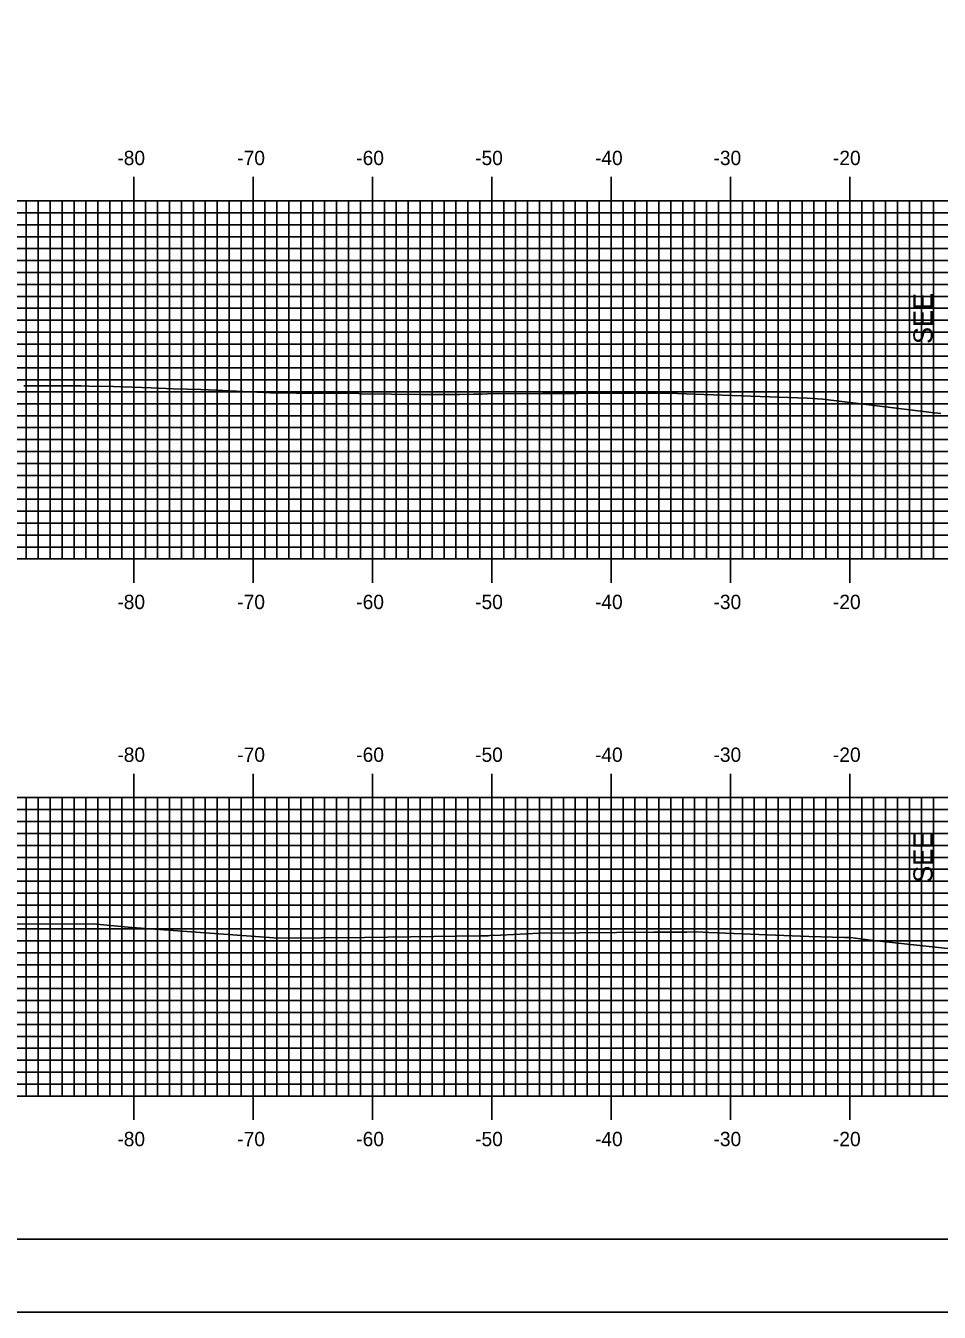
# Model space of a CAD drawing. Extents: x 1686373 to 1686716, y 461260 to 461480.
# Drawn here: x 1686449.7 to 1686526.3, y 461260 to 461367.7 of the extents above; entities that cross this region are included whole.
import ezdxf

# ---------------------------------------------------------------- set-up
doc = ezdxf.new("R2010")
doc.units = 0
for name, color, linetype in [('ANNOTATION', 7, 'Continuous'), ('BORDER', 7, 'Continuous'), ('D_Roadway_Centerline', 7, 'Continuous'), ('H_V ANNOTATION', 7, 'Continuous'), ('M_Roadway_Centerline', 7, 'Continuous'), ('MAJOR', 7, 'Continuous'), ('MINOR', 7, 'Continuous'), ('PLOT BOUNDARY', 7, 'Continuous'), ('S_Roadway_Centerline', 7, 'Continuous')]:
    doc.layers.add(name, color=color, linetype=linetype)

msp = doc.modelspace()

# ---------------------------------------------------------------- linework, layer by layer
at = {"layer": 'BORDER'}
msp.add_lwpolyline([(1686389.17, 461266.07), (1686709.17, 461266.07), (1686709.17, 461476.07), (1686389.17, 461476.07)], close=True, dxfattribs=at)
at = {"layer": 'MAJOR'}
for p, q in [((1686458.77, 461355.08), (1686458.77, 461353.07)), ((1686468.77, 461355.08), (1686468.77, 461353.07)), ((1686478.77, 461355.08), (1686478.77, 461353.07)), ((1686488.77, 461355.08), (1686488.77, 461353.07)), ((1686498.77, 461355.08), (1686498.77, 461353.07)), ((1686508.77, 461355.08), (1686508.77, 461353.07)), ((1686518.77, 461355.08), (1686518.77, 461353.07)), ((1686398.77, 461353.07), (1686678.77, 461353.07)), ((1686398.77, 461353.07), (1686678.77, 461353.07)), ((1686458.77, 461323.07), (1686458.77, 461353.07)), ((1686468.77, 461323.07), (1686468.77, 461353.07)), ((1686478.77, 461323.07), (1686478.77, 461353.07)), ((1686488.77, 461323.07), (1686488.77, 461353.07)), ((1686498.77, 461323.07), (1686498.77, 461353.07)), ((1686508.77, 461323.07), (1686508.77, 461353.07)), ((1686518.77, 461323.07), (1686518.77, 461353.07)), ((1686398.77, 461348.07), (1686678.77, 461348.07)), ((1686398.77, 461343.07), (1686678.77, 461343.07)), ((1686398.77, 461338.07), (1686678.77, 461338.07)), ((1686398.77, 461333.07), (1686678.77, 461333.07)), ((1686398.77, 461328.07), (1686678.77, 461328.07)), ((1686398.77, 461323.07), (1686678.77, 461323.07)), ((1686398.77, 461323.07), (1686678.77, 461323.07)), ((1686458.77, 461321.07), (1686458.77, 461323.07)), ((1686468.77, 461321.07), (1686468.77, 461323.07)), ((1686478.77, 461321.07), (1686478.77, 461323.07)), ((1686488.77, 461321.07), (1686488.77, 461323.07)), ((1686498.77, 461321.07), (1686498.77, 461323.07)), ((1686508.77, 461321.07), (1686508.77, 461323.07)), ((1686518.77, 461321.07), (1686518.77, 461323.07)), ((1686458.77, 461305.08), (1686458.77, 461303.07)), ((1686468.77, 461305.08), (1686468.77, 461303.07)), ((1686478.77, 461305.08), (1686478.77, 461303.07)), ((1686488.77, 461305.08), (1686488.77, 461303.07)), ((1686498.77, 461305.08), (1686498.77, 461303.07)), ((1686508.77, 461305.08), (1686508.77, 461303.07)), ((1686518.77, 461305.08), (1686518.77, 461303.07)), ((1686398.77, 461303.07), (1686678.77, 461303.07)), ((1686398.77, 461303.07), (1686678.77, 461303.07)), ((1686458.77, 461278.07), (1686458.77, 461303.07)), ((1686468.77, 461278.07), (1686468.77, 461303.07)), ((1686478.77, 461278.07), (1686478.77, 461303.07)), ((1686488.77, 461278.07), (1686488.77, 461303.07)), ((1686498.77, 461278.07), (1686498.77, 461303.07)), ((1686508.77, 461278.07), (1686508.77, 461303.07)), ((1686518.77, 461278.07), (1686518.77, 461303.07)), ((1686398.77, 461298.07), (1686678.77, 461298.07)), ((1686398.77, 461293.07), (1686678.77, 461293.07)), ((1686398.77, 461288.07), (1686678.77, 461288.07)), ((1686398.77, 461283.07), (1686678.77, 461283.07)), ((1686398.77, 461278.07), (1686678.77, 461278.07)), ((1686398.77, 461278.07), (1686678.77, 461278.07)), ((1686458.77, 461276.07), (1686458.77, 461278.07)), ((1686468.77, 461276.07), (1686468.77, 461278.07)), ((1686478.77, 461276.07), (1686478.77, 461278.07)), ((1686488.77, 461276.07), (1686488.77, 461278.07)), ((1686498.77, 461276.07), (1686498.77, 461278.07)), ((1686508.77, 461276.07), (1686508.77, 461278.07)), ((1686518.77, 461276.07), (1686518.77, 461278.07))]:
    msp.add_line(p, q, dxfattribs=at)
at = {"layer": 'MINOR'}
for p, q in [((1686398.77, 461352.07), (1686678.77, 461352.07)), ((1686449.77, 461323.07), (1686449.77, 461353.07)), ((1686450.77, 461323.07), (1686450.77, 461353.07)), ((1686451.77, 461323.07), (1686451.77, 461353.07)), ((1686452.77, 461323.07), (1686452.77, 461353.07)), ((1686453.77, 461323.07), (1686453.77, 461353.07)), ((1686454.77, 461323.07), (1686454.77, 461353.07)), ((1686455.77, 461323.07), (1686455.77, 461353.07)), ((1686456.77, 461323.07), (1686456.77, 461353.07)), ((1686457.77, 461323.07), (1686457.77, 461353.07)), ((1686459.77, 461323.07), (1686459.77, 461353.07)), ((1686460.77, 461323.07), (1686460.77, 461353.07)), ((1686461.77, 461323.07), (1686461.77, 461353.07)), ((1686462.77, 461323.07), (1686462.77, 461353.07)), ((1686463.77, 461323.07), (1686463.77, 461353.07)), ((1686464.77, 461323.07), (1686464.77, 461353.07)), ((1686465.77, 461323.07), (1686465.77, 461353.07)), ((1686466.77, 461323.07), (1686466.77, 461353.07)), ((1686467.77, 461323.07), (1686467.77, 461353.07)), ((1686469.77, 461323.07), (1686469.77, 461353.07)), ((1686470.77, 461323.07), (1686470.77, 461353.07)), ((1686471.77, 461323.07), (1686471.77, 461353.07)), ((1686472.77, 461323.07), (1686472.77, 461353.07)), ((1686473.77, 461323.07), (1686473.77, 461353.07)), ((1686474.77, 461323.07), (1686474.77, 461353.07)), ((1686475.77, 461323.07), (1686475.77, 461353.07)), ((1686476.77, 461323.07), (1686476.77, 461353.07)), ((1686477.77, 461323.07), (1686477.77, 461353.07)), ((1686479.77, 461323.07), (1686479.77, 461353.07)), ((1686480.77, 461323.07), (1686480.77, 461353.07)), ((1686481.77, 461323.07), (1686481.77, 461353.07)), ((1686482.77, 461323.07), (1686482.77, 461353.07)), ((1686483.77, 461323.07), (1686483.77, 461353.07)), ((1686484.77, 461323.07), (1686484.77, 461353.07)), ((1686485.77, 461323.07), (1686485.77, 461353.07)), ((1686486.77, 461323.07), (1686486.77, 461353.07)), ((1686487.77, 461323.07), (1686487.77, 461353.07)), ((1686489.77, 461323.07), (1686489.77, 461353.07)), ((1686490.77, 461323.07), (1686490.77, 461353.07)), ((1686491.77, 461323.07), (1686491.77, 461353.07)), ((1686492.77, 461323.07), (1686492.77, 461353.07)), ((1686493.77, 461323.07), (1686493.77, 461353.07)), ((1686494.77, 461323.07), (1686494.77, 461353.07)), ((1686495.77, 461323.07), (1686495.77, 461353.07)), ((1686496.77, 461323.07), (1686496.77, 461353.07)), ((1686497.77, 461323.07), (1686497.77, 461353.07)), ((1686499.77, 461323.07), (1686499.77, 461353.07)), ((1686500.77, 461323.07), (1686500.77, 461353.07)), ((1686501.77, 461323.07), (1686501.77, 461353.07)), ((1686502.77, 461323.07), (1686502.77, 461353.07)), ((1686503.77, 461323.07), (1686503.77, 461353.07)), ((1686504.77, 461323.07), (1686504.77, 461353.07)), ((1686505.77, 461323.07), (1686505.77, 461353.07)), ((1686506.77, 461323.07), (1686506.77, 461353.07)), ((1686507.77, 461323.07), (1686507.77, 461353.07)), ((1686509.77, 461323.07), (1686509.77, 461353.07)), ((1686510.77, 461323.07), (1686510.77, 461353.07)), ((1686511.77, 461323.07), (1686511.77, 461353.07)), ((1686512.77, 461323.07), (1686512.77, 461353.07)), ((1686513.77, 461323.07), (1686513.77, 461353.07)), ((1686514.77, 461323.07), (1686514.77, 461353.07)), ((1686515.77, 461323.07), (1686515.77, 461353.07)), ((1686516.77, 461323.07), (1686516.77, 461353.07)), ((1686517.77, 461323.07), (1686517.77, 461353.07)), ((1686519.77, 461323.07), (1686519.77, 461353.07)), ((1686520.77, 461323.07), (1686520.77, 461353.07)), ((1686521.77, 461323.07), (1686521.77, 461353.07)), ((1686522.77, 461323.07), (1686522.77, 461353.07)), ((1686523.77, 461323.07), (1686523.77, 461353.07)), ((1686524.77, 461323.07), (1686524.77, 461353.07)), ((1686525.77, 461323.07), (1686525.77, 461353.07)), ((1686398.77, 461351.07), (1686678.77, 461351.07)), ((1686398.77, 461350.07), (1686678.77, 461350.07)), ((1686398.77, 461349.07), (1686678.77, 461349.07)), ((1686398.77, 461347.07), (1686678.77, 461347.07)), ((1686398.77, 461346.07), (1686678.77, 461346.07)), ((1686398.77, 461345.07), (1686678.77, 461345.07)), ((1686398.77, 461344.07), (1686678.77, 461344.07)), ((1686398.77, 461342.07), (1686678.77, 461342.07)), ((1686398.77, 461341.07), (1686678.77, 461341.07)), ((1686398.77, 461340.07), (1686678.77, 461340.07)), ((1686398.77, 461339.07), (1686678.77, 461339.07)), ((1686398.77, 461337.07), (1686678.77, 461337.07)), ((1686398.77, 461336.07), (1686678.77, 461336.07)), ((1686398.77, 461335.07), (1686678.77, 461335.07)), ((1686398.77, 461334.07), (1686678.77, 461334.07)), ((1686398.77, 461332.07), (1686678.77, 461332.07)), ((1686398.77, 461331.07), (1686678.77, 461331.07)), ((1686398.77, 461330.07), (1686678.77, 461330.07)), ((1686398.77, 461329.07), (1686678.77, 461329.07)), ((1686398.77, 461327.07), (1686678.77, 461327.07)), ((1686398.77, 461326.07), (1686678.77, 461326.07)), ((1686398.77, 461325.07), (1686678.77, 461325.07)), ((1686398.77, 461324.07), (1686678.77, 461324.07)), ((1686449.77, 461278.07), (1686449.77, 461303.07)), ((1686450.77, 461278.07), (1686450.77, 461303.07)), ((1686451.77, 461278.07), (1686451.77, 461303.07)), ((1686452.77, 461278.07), (1686452.77, 461303.07)), ((1686453.77, 461278.07), (1686453.77, 461303.07)), ((1686454.77, 461278.07), (1686454.77, 461303.07)), ((1686455.77, 461278.07), (1686455.77, 461303.07)), ((1686456.77, 461278.07), (1686456.77, 461303.07)), ((1686457.77, 461278.07), (1686457.77, 461303.07)), ((1686459.77, 461278.07), (1686459.77, 461303.07)), ((1686460.77, 461278.07), (1686460.77, 461303.07)), ((1686461.77, 461278.07), (1686461.77, 461303.07)), ((1686462.77, 461278.07), (1686462.77, 461303.07)), ((1686463.77, 461278.07), (1686463.77, 461303.07)), ((1686464.77, 461278.07), (1686464.77, 461303.07)), ((1686465.77, 461278.07), (1686465.77, 461303.07)), ((1686466.77, 461278.07), (1686466.77, 461303.07)), ((1686467.77, 461278.07), (1686467.77, 461303.07)), ((1686469.77, 461278.07), (1686469.77, 461303.07)), ((1686470.77, 461278.07), (1686470.77, 461303.07)), ((1686471.77, 461278.07), (1686471.77, 461303.07)), ((1686472.77, 461278.07), (1686472.77, 461303.07)), ((1686473.77, 461278.07), (1686473.77, 461303.07)), ((1686474.77, 461278.07), (1686474.77, 461303.07)), ((1686475.77, 461278.07), (1686475.77, 461303.07)), ((1686476.77, 461278.07), (1686476.77, 461303.07)), ((1686477.77, 461278.07), (1686477.77, 461303.07)), ((1686479.77, 461278.07), (1686479.77, 461303.07)), ((1686480.77, 461278.07), (1686480.77, 461303.07)), ((1686481.77, 461278.07), (1686481.77, 461303.07)), ((1686482.77, 461278.07), (1686482.77, 461303.07)), ((1686483.77, 461278.07), (1686483.77, 461303.07)), ((1686484.77, 461278.07), (1686484.77, 461303.07)), ((1686485.77, 461278.07), (1686485.77, 461303.07)), ((1686486.77, 461278.07), (1686486.77, 461303.07)), ((1686487.77, 461278.07), (1686487.77, 461303.07)), ((1686489.77, 461278.07), (1686489.77, 461303.07)), ((1686490.77, 461278.07), (1686490.77, 461303.07)), ((1686491.77, 461278.07), (1686491.77, 461303.07)), ((1686492.77, 461278.07), (1686492.77, 461303.07)), ((1686493.77, 461278.07), (1686493.77, 461303.07)), ((1686494.77, 461278.07), (1686494.77, 461303.07)), ((1686495.77, 461278.07), (1686495.77, 461303.07)), ((1686496.77, 461278.07), (1686496.77, 461303.07)), ((1686497.77, 461278.07), (1686497.77, 461303.07)), ((1686499.77, 461278.07), (1686499.77, 461303.07)), ((1686500.77, 461278.07), (1686500.77, 461303.07)), ((1686501.77, 461278.07), (1686501.77, 461303.07)), ((1686502.77, 461278.07), (1686502.77, 461303.07)), ((1686503.77, 461278.07), (1686503.77, 461303.07)), ((1686504.77, 461278.07), (1686504.77, 461303.07)), ((1686505.77, 461278.07), (1686505.77, 461303.07)), ((1686506.77, 461278.07), (1686506.77, 461303.07)), ((1686507.77, 461278.07), (1686507.77, 461303.07)), ((1686509.77, 461278.07), (1686509.77, 461303.07)), ((1686510.77, 461278.07), (1686510.77, 461303.07)), ((1686511.77, 461278.07), (1686511.77, 461303.07)), ((1686512.77, 461278.07), (1686512.77, 461303.07)), ((1686513.77, 461278.07), (1686513.77, 461303.07)), ((1686514.77, 461278.07), (1686514.77, 461303.07)), ((1686515.77, 461278.07), (1686515.77, 461303.07)), ((1686516.77, 461278.07), (1686516.77, 461303.07)), ((1686517.77, 461278.07), (1686517.77, 461303.07)), ((1686519.77, 461278.07), (1686519.77, 461303.07)), ((1686520.77, 461278.07), (1686520.77, 461303.07)), ((1686521.77, 461278.07), (1686521.77, 461303.07)), ((1686522.77, 461278.07), (1686522.77, 461303.07)), ((1686523.77, 461278.07), (1686523.77, 461303.07)), ((1686524.77, 461278.07), (1686524.77, 461303.07)), ((1686525.77, 461278.07), (1686525.77, 461303.07)), ((1686398.77, 461302.07), (1686678.77, 461302.07)), ((1686398.77, 461301.07), (1686678.77, 461301.07)), ((1686398.77, 461300.07), (1686678.77, 461300.07)), ((1686398.77, 461299.07), (1686678.77, 461299.07)), ((1686398.77, 461297.07), (1686678.77, 461297.07)), ((1686398.77, 461296.07), (1686678.77, 461296.07)), ((1686398.77, 461295.07), (1686678.77, 461295.07)), ((1686398.77, 461294.07), (1686678.77, 461294.07)), ((1686398.77, 461292.07), (1686678.77, 461292.07)), ((1686398.77, 461291.07), (1686678.77, 461291.07)), ((1686398.77, 461290.07), (1686678.77, 461290.07)), ((1686398.77, 461289.07), (1686678.77, 461289.07)), ((1686398.77, 461287.07), (1686678.77, 461287.07)), ((1686398.77, 461286.07), (1686678.77, 461286.07)), ((1686398.77, 461285.07), (1686678.77, 461285.07)), ((1686398.77, 461284.07), (1686678.77, 461284.07)), ((1686398.77, 461282.07), (1686678.77, 461282.07)), ((1686398.77, 461281.07), (1686678.77, 461281.07)), ((1686398.77, 461280.07), (1686678.77, 461280.07)), ((1686398.77, 461279.07), (1686678.77, 461279.07))]:
    msp.add_line(p, q, dxfattribs=at)
at = {"layer": 'PLOT BOUNDARY'}
msp.add_lwpolyline([(1686372.98, 461259.95), (1686712.98, 461259.95), (1686712.98, 461479.95), (1686372.98, 461479.95)], close=True, dxfattribs=at)
at = {"layer": 'S_Roadway_Centerline'}
for points in [[(1686449.57, 461337.57), (1686454.38, 461337.57), (1686455, 461337.56), (1686457.09, 461337.51), (1686460.24, 461337.4), (1686462.11, 461337.33), (1686464.4, 461337.26), (1686465.68, 461337.22), (1686470.24, 461336.98), (1686472.42, 461336.96), (1686472.66, 461336.96), (1686472.8, 461336.96), (1686475.81, 461336.95), (1686477.64, 461336.92), (1686477.86, 461336.91), (1686482.88, 461336.84), (1686486.06, 461336.85), (1686487.24, 461336.87), (1686487.9, 461336.88), (1686488.41, 461336.9), (1686493.04, 461336.92), (1686495.94, 461336.94), (1686503.64, 461336.96), (1686505.75, 461336.88), (1686515.19, 461336.53), (1686516.5, 461336.47), (1686525.62, 461335.35), (1686526.4, 461335.25)], [(1686446.23, 461292.52), (1686449.76, 461292.48), (1686455.36, 461292.5), (1686458.01, 461292.25), (1686458.93, 461292.16), (1686458.99, 461292.16), (1686470.91, 461291.29), (1686478.12, 461291.34), (1686487.77, 461291.48), (1686488.46, 461291.5), (1686488.6, 461291.51), (1686489.49, 461291.55), (1686492.76, 461291.72), (1686496.09, 461291.75), (1686502.36, 461291.79), (1686505.11, 461291.8), (1686505.94, 461291.84), (1686506.97, 461291.76), (1686515.33, 461291.45), (1686518.34, 461291.36), (1686518.82, 461291.35), (1686520.51, 461291.14), (1686531.38, 461289.95)]]:
    msp.add_lwpolyline(points, dxfattribs=at)

# ---------------------------------------------------------------- texts
at = {"layer": 'ANNOTATION'}
for p in [(1686525.7, 461341.08), (1686525.7, 461295.94)]:
    msp.add_text('SEE', height=1.6, rotation=90, dxfattribs=at).set_placement(p)
at = {"layer": 'D_Roadway_Centerline'}
for s, p in [('C', (1686509.17, 461336.35)), ('L', (1686509.18, 461336.34))]:
    msp.add_text(s, height=0.0146, dxfattribs=at).set_placement(p)
at = {"layer": 'H_V ANNOTATION'}
for s, p in [('-80', (1686457.4, 461356.07)), ('-70', (1686467.45, 461356.07)), ('-60', (1686477.42, 461356.07)), ('-50', (1686487.38, 461356.07)), ('-40', (1686497.42, 461356.07)), ('-30', (1686507.35, 461356.07)), ('-20', (1686517.36, 461356.07)), ('-80', (1686457.4, 461318.87)), ('-70', (1686467.45, 461318.87)), ('-60', (1686477.42, 461318.87)), ('-50', (1686487.38, 461318.87)), ('-40', (1686497.42, 461318.87)), ('-30', (1686507.35, 461318.87)), ('-20', (1686517.36, 461318.87)), ('-80', (1686457.4, 461306.07)), ('-70', (1686467.45, 461306.07)), ('-60', (1686477.42, 461306.07)), ('-50', (1686487.38, 461306.07)), ('-40', (1686497.42, 461306.07)), ('-30', (1686507.35, 461306.07)), ('-20', (1686517.36, 461306.07)), ('-80', (1686457.4, 461273.87)), ('-70', (1686467.45, 461273.87)), ('-60', (1686477.42, 461273.87)), ('-50', (1686487.38, 461273.87)), ('-40', (1686497.42, 461273.87)), ('-30', (1686507.35, 461273.87)), ('-20', (1686517.36, 461273.87))]:
    msp.add_text(s, height=1.2, dxfattribs=at).set_placement(p)
at = {"layer": 'M_Roadway_Centerline'}
for s, p in [('C', (1686503.63, 461336.96)), ('L', (1686503.64, 461336.95)), ('C', (1686505.94, 461291.84)), ('L', (1686505.94, 461291.83))]:
    msp.add_text(s, height=0.0146, dxfattribs=at).set_placement(p)

doc.saveas('drawing.dxf')
